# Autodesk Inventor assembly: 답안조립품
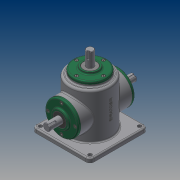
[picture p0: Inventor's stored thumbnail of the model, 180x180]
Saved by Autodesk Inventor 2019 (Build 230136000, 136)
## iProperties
Created: 2019-03
Part Number: 답안조립품
Material: 일반
Document SubType Name: Assembly
Designer: PC312-19
Author: PC312-19
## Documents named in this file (16)
- C:\Users\PC312-19\Desktop\490314V1003\답안조립품.iam
- C:\Users\PC312-19\Desktop\490314V1003\본체.ipt
- C:\Users\PC312-19\Desktop\490314V1003\커버.ipt
- C:\Users\PC312-19\Desktop\490314V1003\볼트 M4.ipt
- 볼트 M4.ipt
- C:\Users\PC312-19\Desktop\490314V1003\오일 실.ipt
- 오일 실.ipt
- C:\Users\PC312-19\Desktop\490314V1003\베어링 6203.ipt
- C:\Users\PC312-19\Desktop\490314V1003\메인 축.ipt
- 메인 축.ipt
- C:\Users\PC312-19\Desktop\490314V1003\서브 축.ipt
- 서브 축.ipt
- C:\Users\PC312-19\Desktop\490314V1003\키 5x5.ipt
- C:\Users\PC312-19\Desktop\490314V1003\키 4x4.ipt
- C:\Users\PC312-19\Desktop\490314V1003\메인 베벨기어.ipt
- C:\Users\PC312-19\Desktop\490314V1003\서브 베벨기어.ipt
